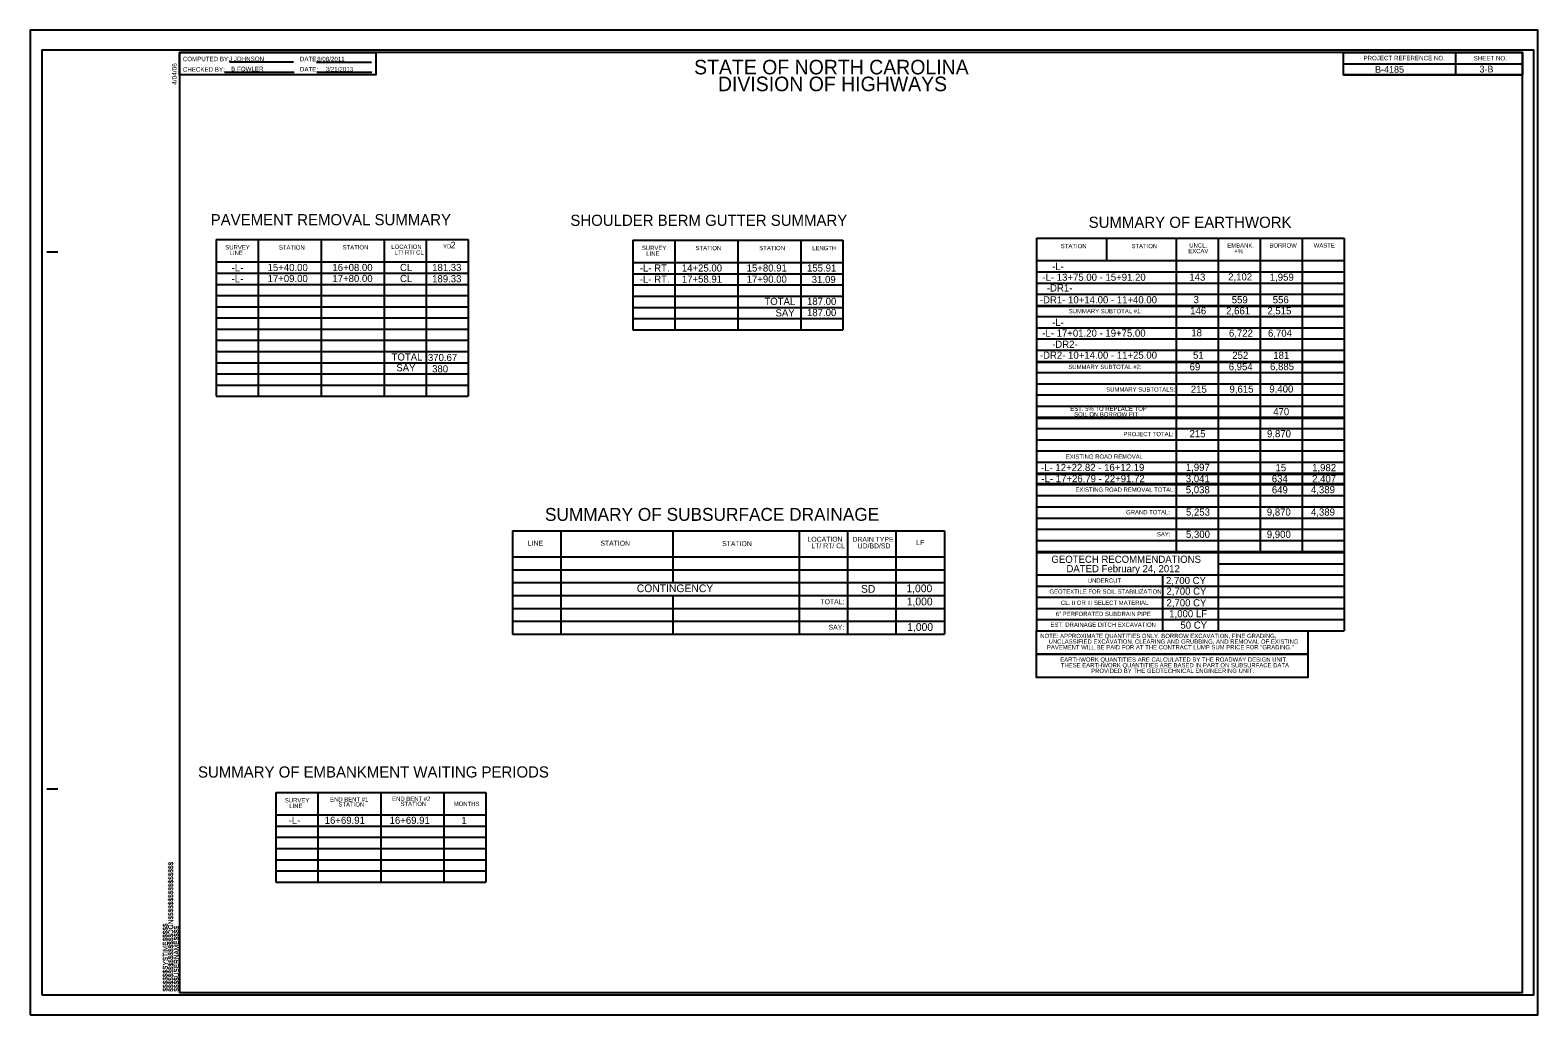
# Model space of a CAD drawing. Extents: x 2530399 to 2530799, y 189629 to 189994.
# Drawn here: x 2530399.3 to 2530567.7, y 189629.1 to 189739.1 of the extents above; entities that cross this region are included whole.
import ezdxf

# ---------------------------------------------------------------- set-up
doc = ezdxf.new("R2010")
doc.units = 0
for name, color, linetype in [('Default', 7, 'Continuous'), ('Old_Level_17', 7, 'Continuous'), ('Old_Level_2', 7, 'Continuous'), ('Old_Level_24', 7, 'Continuous'), ('Old_Level_29', 7, 'Continuous'), ('Old_Level_30', 7, 'Continuous'), ('Old_Level_41', 7, 'Continuous'), ('Prop Grid Mask', 7, 'Continuous'), ('Prop XSC Text', 7, 'Continuous'), ('Sheet Border Standard 30in CELL', 7, 'Continuous'), ('Sheet Summary Combination CELL', 7, 'Continuous'), ('Sheet Summary Combination Grid CELL', 7, 'Continuous')]:
    doc.layers.add(name, color=color, linetype=linetype)

msp = doc.modelspace()

# ---------------------------------------------------------------- linework, layer by layer
at = {"layer": 'Old_Level_2'}
for p, q in [((2530567.7, 189739.09), (2530399.3, 189739.09)), ((2530399.3, 189739.09), (2530399.3, 189629.09)), ((2530399.3, 189629.09), (2530567.7, 189629.09))]:
    msp.add_line(p, q, dxfattribs=at)
at = {"layer": 'Old_Level_24'}
for p, q in [((2530558.5, 189736.58), (2530558.5, 189734.08)), ((2530558.5, 189736.58), (2530558.5, 189734.08)), ((2530421.57, 189735.55), (2530428.72, 189735.55)), ((2530431.3, 189735.53), (2530437.44, 189735.53)), ((2530546, 189735.33), (2530566, 189735.33)), ((2530546, 189735.33), (2530566, 189735.33)), ((2530421.02, 189734.38), (2530428.79, 189734.38)), ((2530431.32, 189734.38), (2530437.46, 189734.38)), ((2530546, 189734.08), (2530566, 189734.08)), ((2530546, 189734.08), (2530566, 189734.08)), ((2530546, 189734.08), (2530566, 189734.08)), ((2530401.15, 189714.34), (2530402.4, 189714.34)), ((2530401.15, 189714.34), (2530402.4, 189714.34)), ((2530401.15, 189654.34), (2530402.4, 189654.34)), ((2530401.15, 189654.34), (2530402.4, 189654.34)), ((2530416, 189631.59), (2530416, 189631.59))]:
    msp.add_line(p, q, dxfattribs=at)
for points in [[(2530566, 189736.59), (2530416, 189736.59), (2530416, 189631.59), (2530566, 189631.59)], [(2530416, 189736.59), (2530437.9, 189736.59), (2530437.9, 189734.09), (2530416, 189734.09)], [(2530546, 189736.59), (2530566, 189736.59), (2530566, 189734.08), (2530546, 189734.08)], [(2530546, 189736.59), (2530566, 189736.59), (2530566, 189734.08), (2530546, 189734.08)]]:
    msp.add_lwpolyline(points, close=True, dxfattribs=at)
at = {"layer": 'Old_Level_29'}
msp.add_lwpolyline([(2530400.6, 189631.33), (2530567.25, 189631.33), (2530567.25, 189736.84), (2530400.6, 189736.84)], close=True, dxfattribs=at)
at = {"layer": 'Old_Level_30'}
msp.add_lwpolyline([(2530399.3, 189629.09), (2530567.7, 189629.09), (2530567.7, 189739.09), (2530399.3, 189739.09)], close=True, dxfattribs=at)
at = {"layer": 'Old_Level_41'}
for p, q in [((2530511.72, 189694.59), (2530546.05, 189694.59)), ((2530511.72, 189693.34), (2530546.05, 189693.34)), ((2530511.72, 189683.34), (2530546.05, 189683.34)), ((2530511.72, 189680.74), (2530546.05, 189680.74)), ((2530511.72, 189678.24), (2530546.05, 189678.24)), ((2530511.72, 189671.99), (2530546.05, 189671.99))]:
    msp.add_line(p, q, dxfattribs=at)
at = {"layer": 'Prop Grid Mask'}
for points in [[(2530511.72, 189671.99), (2530542.02, 189671.99), (2530542.02, 189669.38), (2530511.72, 189669.38)], [(2530511.72, 189669.38), (2530542.02, 189669.38), (2530542.02, 189666.77), (2530511.72, 189666.77)]]:
    msp.add_lwpolyline(points, close=True, dxfattribs=at)
at = {"layer": 'Sheet Summary Combination CELL'}
for p, q in [((2530434.21, 189715.68), (2530434.21, 189715.68)), ((2530434.83, 189715.67), (2530434.83, 189715.67)), ((2530435.74, 189715.69), (2530435.74, 189715.69)), ((2530436.3, 189715.68), (2530436.3, 189715.68)), ((2530480.74, 189715.61), (2530480.74, 189715.61)), ((2530481.37, 189715.6), (2530481.37, 189715.6)), ((2530482.27, 189715.62), (2530482.27, 189715.62)), ((2530482.83, 189715.61), (2530482.83, 189715.61)), ((2530522.66, 189715.83), (2530522.66, 189715.83)), ((2530523.28, 189715.82), (2530523.28, 189715.82)), ((2530524.19, 189715.84), (2530524.19, 189715.84)), ((2530524.75, 189715.83), (2530524.75, 189715.83)), ((2530473.86, 189683.14), (2530473.86, 189683.14)), ((2530474.58, 189683.12), (2530474.58, 189683.12)), ((2530481.64, 189683.15), (2530481.64, 189683.15)), ((2530482.28, 189683.14), (2530482.28, 189683.14)), ((2530440.86, 189653.91), (2530440.86, 189653.91)), ((2530441.48, 189653.9), (2530441.48, 189653.9)), ((2530442.39, 189653.92), (2530442.39, 189653.92)), ((2530442.95, 189653.91), (2530442.95, 189653.91))]:
    msp.add_line(p, q, dxfattribs=at)
at = {"layer": 'Sheet Summary Combination Grid CELL'}
for p, q in [((2530420.08, 189715.69), (2530448.22, 189715.69)), ((2530420.08, 189715.69), (2530420.08, 189698.19)), ((2530424.77, 189715.69), (2530424.77, 189698.19)), ((2530431.81, 189715.69), (2530431.81, 189698.19)), ((2530438.84, 189715.69), (2530438.84, 189698.19)), ((2530443.53, 189715.69), (2530443.53, 189698.19)), ((2530448.22, 189715.69), (2530448.22, 189698.19)), ((2530466.62, 189715.62), (2530490.06, 189715.62)), ((2530466.62, 189715.62), (2530466.62, 189705.62)), ((2530471.31, 189715.62), (2530471.31, 189705.62)), ((2530478.34, 189715.62), (2530478.34, 189705.62)), ((2530485.37, 189715.62), (2530485.37, 189705.62)), ((2530490.06, 189715.62), (2530490.06, 189705.62)), ((2530511.72, 189715.84), (2530546.05, 189715.84)), ((2530511.72, 189715.84), (2530511.72, 189677.09)), ((2530519.51, 189715.84), (2530519.51, 189713.34)), ((2530527.29, 189715.84), (2530527.29, 189713.34)), ((2530531.98, 189715.84), (2530531.98, 189680.74)), ((2530536.67, 189715.84), (2530536.67, 189680.74)), ((2530541.36, 189715.84), (2530541.36, 189680.74)), ((2530546.05, 189715.84), (2530546.05, 189671.99)), ((2530420.08, 189713.19), (2530448.22, 189713.19)), ((2530466.62, 189713.12), (2530490.06, 189713.12)), ((2530511.72, 189713.34), (2530546.05, 189713.34)), ((2530527.29, 189713.34), (2530527.29, 189680.74)), ((2530420.08, 189711.94), (2530448.22, 189711.94)), ((2530466.62, 189711.87), (2530490.06, 189711.87)), ((2530511.72, 189712.09), (2530546.05, 189712.09)), ((2530420.08, 189710.69), (2530448.22, 189710.69)), ((2530420.08, 189709.44), (2530448.22, 189709.44)), ((2530466.62, 189710.62), (2530490.06, 189710.62)), ((2530466.62, 189709.37), (2530490.06, 189709.37)), ((2530511.72, 189710.84), (2530546.05, 189710.84)), ((2530511.72, 189710.84), (2530546.05, 189710.84)), ((2530511.72, 189709.59), (2530546.05, 189709.59)), ((2530420.08, 189708.19), (2530448.22, 189708.19)), ((2530466.62, 189708.12), (2530490.06, 189708.12)), ((2530511.72, 189708.34), (2530546.05, 189708.34)), ((2530511.72, 189708.24), (2530546.05, 189708.24)), ((2530420.08, 189706.94), (2530448.22, 189706.94)), ((2530466.62, 189706.87), (2530490.06, 189706.87)), ((2530511.72, 189707.09), (2530546.05, 189707.09)), ((2530511.72, 189707.09), (2530546.05, 189707.09)), ((2530420.08, 189705.69), (2530448.22, 189705.69)), ((2530420.08, 189704.44), (2530448.22, 189704.44)), ((2530466.62, 189705.62), (2530490.06, 189705.62)), ((2530511.72, 189705.84), (2530546.05, 189705.84)), ((2530511.72, 189704.59), (2530546.05, 189704.59)), ((2530420.08, 189703.19), (2530448.22, 189703.19)), ((2530511.72, 189703.34), (2530546.05, 189703.34)), ((2530420.08, 189701.94), (2530448.22, 189701.94)), ((2530511.72, 189702.09), (2530546.05, 189702.09)), ((2530511.72, 189701.99), (2530546.05, 189701.99)), ((2530420.08, 189700.69), (2530448.22, 189700.69)), ((2530420.08, 189699.44), (2530448.22, 189699.44)), ((2530511.72, 189700.84), (2530546.05, 189700.84)), ((2530511.72, 189699.59), (2530546.05, 189699.59)), ((2530420.08, 189698.19), (2530448.22, 189698.19)), ((2530511.72, 189698.34), (2530546.05, 189698.34)), ((2530511.72, 189697.09), (2530546.05, 189697.09)), ((2530511.72, 189695.84), (2530546.05, 189695.84)), ((2530511.72, 189695.74), (2530546.05, 189695.74)), ((2530511.72, 189692.09), (2530546.05, 189692.09)), ((2530511.72, 189690.84), (2530546.05, 189690.84)), ((2530511.72, 189689.59), (2530546.05, 189689.59)), ((2530511.72, 189689.49), (2530546.05, 189689.49)), ((2530511.72, 189688.44), (2530546.05, 189688.44)), ((2530511.72, 189688.34), (2530546.05, 189688.34)), ((2530511.72, 189687.09), (2530546.05, 189687.09)), ((2530511.72, 189685.84), (2530546.05, 189685.84)), ((2530511.72, 189684.59), (2530546.05, 189684.59)), ((2530453.19, 189683.14), (2530501.42, 189683.14)), ((2530453.19, 189683.14), (2530453.19, 189671.62)), ((2530458.59, 189683.14), (2530458.59, 189671.62)), ((2530471.1, 189683.14), (2530471.1, 189677.38)), ((2530485.21, 189683.14), (2530485.21, 189671.62)), ((2530490.61, 189683.14), (2530490.61, 189671.62)), ((2530496.01, 189683.14), (2530496.01, 189671.62)), ((2530501.42, 189683.14), (2530501.42, 189671.62)), ((2530511.72, 189682.09), (2530546.05, 189682.09)), ((2530511.72, 189682.09), (2530546.05, 189682.09)), ((2530511.72, 189680.84), (2530546.05, 189680.84)), ((2530511.72, 189680.74), (2530511.72, 189671.99)), ((2530511.72, 189680.74), (2530546.05, 189680.74)), ((2530531.98, 189680.74), (2530531.98, 189671.99)), ((2530453.19, 189680.26), (2530501.42, 189680.26)), ((2530531.98, 189679.49), (2530546.05, 189679.49)), ((2530453.19, 189678.82), (2530501.42, 189678.82)), ((2530453.19, 189677.38), (2530501.42, 189677.38)), ((2530511.72, 189678.24), (2530546.05, 189678.24)), ((2530525.79, 189678.24), (2530525.79, 189671.99)), ((2530453.19, 189675.94), (2530501.42, 189675.94)), ((2530457.59, 189675.94), (2530490, 189675.94)), ((2530471.1, 189675.94), (2530471.1, 189671.62)), ((2530511.72, 189676.99), (2530546.05, 189676.99)), ((2530511.72, 189675.74), (2530546.05, 189675.74)), ((2530453.19, 189674.5), (2530501.42, 189674.5)), ((2530457.59, 189674.5), (2530490, 189674.5)), ((2530511.72, 189674.49), (2530546.05, 189674.49)), ((2530453.19, 189673.06), (2530501.42, 189673.06)), ((2530457.59, 189673.06), (2530490, 189673.06)), ((2530511.72, 189673.24), (2530546.05, 189673.24)), ((2530453.19, 189671.62), (2530501.42, 189671.62)), ((2530511.72, 189671.99), (2530531.62, 189671.99)), ((2530426.73, 189653.92), (2530450.18, 189653.92)), ((2530426.73, 189653.92), (2530426.73, 189643.92)), ((2530431.42, 189653.92), (2530431.42, 189643.92)), ((2530438.46, 189653.92), (2530438.46, 189643.92)), ((2530445.49, 189653.92), (2530445.49, 189643.92)), ((2530450.18, 189653.92), (2530450.18, 189643.92)), ((2530426.73, 189651.42), (2530450.18, 189651.42)), ((2530426.73, 189650.17), (2530450.18, 189650.17)), ((2530426.73, 189648.92), (2530450.18, 189648.92)), ((2530426.73, 189647.67), (2530450.18, 189647.67)), ((2530426.73, 189646.42), (2530450.18, 189646.42)), ((2530426.73, 189645.17), (2530450.18, 189645.17)), ((2530426.73, 189643.92), (2530450.18, 189643.92))]:
    msp.add_line(p, q, dxfattribs=at)

# ---------------------------------------------------------------- texts
at = {"layer": 'Default'}
for s, p in [('EARTHWORK QUANTITIES ARE CALCULATED BY THE ROADWAY DESIGN UNIT. ', (2530514.35, 189668.54)), ('THESE EARTHWORK QUANTITIES ARE BASED IN PART ON SUBSURFACE DATA ', (2530514.42, 189667.91)), ('PROVIDED BY THE GEOTECHNICAL ENGINEERING UNIT.', (2530517.81, 189667.28))]:
    msp.add_text(s, height=0.48, dxfattribs=at).set_placement(p)
at = {"layer": 'Old_Level_17'}
for s, height, p in [('J JOHNSON             ', 0.5, (2530421.51, 189735.63)), ('B FOWLER             ', 0.5, (2530421.76, 189734.5)), ('3/08/2011         ', 0.5, (2530431.36, 189735.61)), ('3/21/2013         ', 0.5, (2530432.31, 189734.48)), ('B-4185   ', 0.75, (2530549.52, 189734.33)), ('3-B', 0.75, (2530561.18, 189734.36))]:
    msp.add_text(s, height=height, dxfattribs=at).set_placement(p)
at = {"layer": 'Old_Level_2'}
for s, p in [('-L-', (2530421.8, 189712.15)), ('15+40.00', (2530425.82, 189712.18)), ('16+08.00', (2530433.06, 189712.18)), ('CL', (2530440.61, 189712.18)), ('181.33', (2530444.2, 189712.18)), ('-L- RT.', (2530467.4, 189712.12)), ('14+25.00', (2530472.09, 189712.12)), ('15+80.91', (2530479.33, 189712.12)), ('155.91', (2530486.07, 189712.12)), ('-L-', (2530513.45, 189712.3)), ('-L-', (2530421.8, 189710.92)), ('17+09.00', (2530425.82, 189710.95)), ('17+80.00', (2530433.06, 189710.95)), ('CL', (2530440.61, 189710.95)), ('189.33', (2530444.2, 189710.92)), ('-L- RT.', (2530467.4, 189710.88)), ('17+58.91', (2530472.09, 189710.88)), ('17+90.00', (2530479.33, 189710.88)), ('31.09', (2530486.6, 189710.84)), ('-L- 13+75.00 - 15+91.20', (2530512.36, 189711.09)), ('143', (2530528.78, 189711.1)), ('2,102', (2530533.11, 189711.13)), ('1,959', (2530537.76, 189711.1)), ('-DR1- 10+14.00 - 11+40.00', (2530512.08, 189708.57)), ('-DR1- ', (2530512.86, 189709.89)), ('3', (2530529.25, 189708.59)), ('559', (2530533.51, 189708.58)), ('556', (2530538.09, 189708.58)), ('TOTAL', (2530481.31, 189708.39)), ('SAY', (2530482.55, 189707.11)), ('187.00', (2530486.07, 189708.39)), ('187.00', (2530486.07, 189707.14)), ('146', (2530528.87, 189707.35)), ('2,661', (2530532.88, 189707.34)), ('2,515', (2530537.49, 189707.34)), ('-L-', (2530513.45, 189706.05)), ('-L- 17+01.20 - 19+75.00', (2530512.35, 189704.85)), ('-DR2-', (2530513.45, 189703.6)), ('18', (2530528.99, 189704.88)), ('6,722', (2530533.2, 189704.85)), ('6,704', (2530537.56, 189704.84)), ('TOTAL', (2530439.67, 189702.18)), ('370.67', (2530443.73, 189702.12)), ('-DR2- 10+14.00 - 11+25.00', (2530512.08, 189702.38)), ('51', (2530529.19, 189702.38)), ('252', (2530533.57, 189702.37)), ('181', (2530538.15, 189702.37)), ('SAY', (2530440.2, 189700.98)), ('380', (2530444.2, 189700.86)), ('69', (2530528.81, 189701.08)), ('6,954', (2530533.17, 189701.1)), ('6,885', (2530537.79, 189701.11)), ('215', (2530528.94, 189698.58)), ('9,615', (2530533.26, 189698.59)), ('9,400', (2530537.71, 189698.61)), ('470', (2530538.14, 189696.07)), ('215', (2530528.8, 189693.61)), ('9,870', (2530537.45, 189693.61)), ('-L- 12+22.82 - 16+12.19', (2530512.21, 189689.84)), ('-L- 17+26.79 - 22+91.72', (2530512.25, 189688.59)), ('3,041', (2530528.38, 189688.59)), ('1,997', (2530528.38, 189689.85)), ('634', (2530537.98, 189688.58)), ('15', (2530538.4, 189689.82)), ('2,407', (2530542.49, 189688.58)), ('1,982', (2530542.49, 189689.82)), ('5,038', (2530528.38, 189687.36)), ('649', (2530537.99, 189687.35)), ('4,389', (2530542.36, 189687.36)), ('5,253', (2530528.4, 189684.86)), ('9,870', (2530537.43, 189684.86)), ('4,389', (2530542.36, 189684.86)), ('5,300', (2530528.4, 189682.37)), ('9,900', (2530537.43, 189682.37)), ('2,700 CY', (2530526.17, 189677.21)), ('2,700 CY', (2530526.22, 189676.02)), ('2,700 CY', (2530526.22, 189674.72)), ('1,000 LF', (2530526.53, 189673.5)), ('50 CY', (2530527.78, 189672.23)), ('-L- ', (2530428.17, 189650.44)), ('16+69.91', (2530432.2, 189650.42)), ('16+69.91', (2530439.45, 189650.42)), ('1', (2530447.47, 189650.4))]:
    msp.add_text(s, height=0.8, dxfattribs=at).set_placement(p)
at = {"layer": 'Old_Level_24'}
for s, p in [('4/04/06', (2530415.68, 189732.98)), ('$$$$$$$$$$$$$$$$DGN$$$$$$$$$$$$$$$$', (2530415.24, 189631.67)), ('$$$$$$$$$$$$$$$$DGN$$$$$$$$$$$$$$$$', (2530415.29, 189631.67)), ('$$$$$$SYSTIME$$$$$', (2530414.63, 189631.69)), ('$$$$$$SYSTIME$$$$$', (2530414.68, 189631.69)), ('$$$$USERNAME$$$$', (2530415.87, 189631.68)), ('$$$$USERNAME$$$$', (2530415.92, 189631.68))]:
    msp.add_text(s, height=0.525, rotation=90, dxfattribs=at).set_placement(p)
for s, height, p in [('COMPUTED BY:', 0.5, (2530416.35, 189735.62)), ('CHECKED BY:', 0.5, (2530416.36, 189734.45)), ('DATE:', 0.5, (2530429.43, 189735.61)), ('DATE:', 0.5, (2530429.43, 189734.47)), ('STATE OF NORTH CAROLINA', 1.625, (2530473.46, 189734.15)), ('PROJECT REFERENCE NO.', 0.5, (2530548.22, 189735.72)), ('PROJECT REFERENCE NO.', 0.5, (2530548.22, 189735.72)), ('SHEET NO.', 0.5, (2530560.53, 189735.71)), ('SHEET NO.', 0.5, (2530560.53, 189735.71)), ('DIVISION OF HIGHWAYS', 1.625, (2530476.12, 189732.27))]:
    msp.add_text(s, height=height, dxfattribs=at).set_placement(p)
at = {"layer": 'Prop XSC Text'}
for s, p in [('NOTE: APPROXIMATE QUANTITIES ONLY. BORROW EXCAVATION, FINE GRADING, ', (2530512.13, 189671.18)), ('     UNCLASSIFIED EXCAVATION, CLEARING AND GRUBBING, AND REMOVAL OF EXISTING ', (2530512.13, 189670.55)), ('    PAVEMENT WILL BE PAID FOR AT THE CONTRACT LUMP SUM PRICE FOR "GRADING."', (2530512.13, 189669.92))]:
    msp.add_text(s, height=0.48, dxfattribs=at).set_placement(p)
at = {"layer": 'Sheet Border Standard 30in CELL'}
for s, p in [('CONTINGENCY', (2530467.06, 189676.31)), ('SD', (2530492.1, 189676.24)), ('1,000', (2530497.17, 189676.3)), ('1,000', (2530497.21, 189674.83)), ('1,000', (2530497.26, 189671.98))]:
    msp.add_text(s, height=0.864, dxfattribs=at).set_placement(p)
at = {"layer": 'Sheet Summary Combination CELL'}
for s, height, p in [('PAVEMENT REMOVAL SUMMARY', 1.25, (2530419.47, 189717.29)), ('SHOULDER BERM GUTTER SUMMARY', 1.25, (2530459.64, 189717.22)), ('SUMMARY OF EARTHWORK', 1.25, (2530517.53, 189717)), ('SUMMARY OF SUBSURFACE DRAINAGE', 1.44, (2530456.8, 189684.27)), ('SUMMARY OF EMBANKMENT WAITING PERIODS', 1.25, (2530418.05, 189655.59))]:
    msp.add_text(s, height=height, rotation=0.0119, dxfattribs=at).set_placement(p)
for s, height, p in [('SURVEY', 0.48, (2530421.1, 189714.59)), ('LINE', 0.48, (2530421.59, 189713.96)), ('STATION', 0.48, (2530427.09, 189714.58)), ('STATION', 0.48, (2530434.2, 189714.59)), ('LOCATION', 0.48, (2530439.64, 189714.65)), ('LT/ RT/ CL', 0.48, (2530440.02, 189714.02)), ('SURVEY', 0.48, (2530467.63, 189714.52)), ('STATION', 0.48, (2530473.62, 189714.51)), ('STATION', 0.48, (2530480.74, 189714.51)), ('LENGTH', 0.48, (2530486.65, 189714.51)), ('STATION', 0.48, (2530514.42, 189714.73)), ('STATION', 0.48, (2530522.31, 189714.73)), ('EXCAV.', 0.48, (2530528.65, 189714.17)), ('UNCL.', 0.48, (2530528.77, 189714.8)), ('EMBANK.', 0.48, (2530533.01, 189714.8)), ('+%', 0.48, (2530533.79, 189714.17)), ('BORROW', 0.48, (2530537.72, 189714.8)), ('WASTE', 0.48, (2530542.67, 189714.8)), ('LINE', 0.48, (2530468.12, 189713.89)), ('SUMMARY SUBTOTAL #1:', 0.48, (2530515.31, 189707.46)), ('SUMMARY SUBTOTAL #2:', 0.48, (2530515.26, 189701.23)), ('SUMMARY SUBTOTALS:', 0.48, (2530519.49, 189698.71)), ('EST. 5% TO REPLACE TOP', 0.48, (2530515.48, 189696.56)), ('SOIL ON BORROW PIT', 0.48, (2530515.91, 189695.93)), ('PROJECT TOTAL:', 0.48, (2530521.41, 189693.73)), ('EXISTING ROAD REMOVAL', 0.48, (2530514.98, 189691.21)), ('EXISTING ROAD REMOVAL TOTAL:', 0.48, (2530516.05, 189687.52)), ('GRAND TOTAL:', 0.48, (2530521.71, 189685)), ('LOCATION', 0.553, (2530486.13, 189681.94)), ('DRAIN TYPE', 0.553, (2530491.15, 189681.93)), ('SAY:', 0.48, (2530525.15, 189682.54)), ('LINE', 0.553, (2530454.89, 189681.51)), ('STATION', 0.553, (2530462.99, 189681.5)), ('STATION', 0.553, (2530476.59, 189681.45)), ('LT/ RT/ CL', 0.553, (2530486.57, 189681.22)), ('UD/BD/SD', 0.553, (2530491.73, 189681.2)), ('LF', 0.553, (2530498.27, 189681.57)), ('GEOTECH RECOMMENDATIONS', 0.8, (2530513.37, 189679.58)), ('DATED February 24, 2012', 0.8, (2530515.05, 189678.53)), ('UNDERCUT', 0.48, (2530517.43, 189677.36)), ('GEOTEXTILE FOR SOIL STABILIZATION', 0.48, (2530513.15, 189676.13)), ('TOTAL:', 0.553, (2530487.57, 189674.96)), ('6" PERFORATED SUBDRAIN PIPE', 0.48, (2530513.85, 189673.64)), ('CL. II OR III SELECT MATERIAL', 0.48, (2530514.44, 189674.88)), ('SAY:', 0.553, (2530488.48, 189672.11)), ('EST. DRAINAGE DITCH EXCAVATION', 0.48, (2530513.26, 189672.43)), ('SURVEY', 0.48, (2530427.75, 189652.82)), ('LINE', 0.48, (2530428.24, 189652.19)), ('END BENT #1', 0.48, (2530432.8, 189652.92)), ('STATION', 0.48, (2530433.74, 189652.36)), ('END BENT #2', 0.48, (2530439.73, 189652.98)), ('STATION', 0.48, (2530440.67, 189652.42)), ('MONTHS', 0.48, (2530446.61, 189652.42))]:
    msp.add_text(s, height=height, dxfattribs=at).set_placement(p)
at = {"layer": 'Sheet Summary Combination Grid CELL'}
for s, height, p in [('YD', 0.48, (2530445.42, 189714.7)), ('2', 0.75, (2530446.26, 189714.7))]:
    msp.add_text(s, height=height, dxfattribs=at).set_placement(p)

doc.saveas('drawing.dxf')
